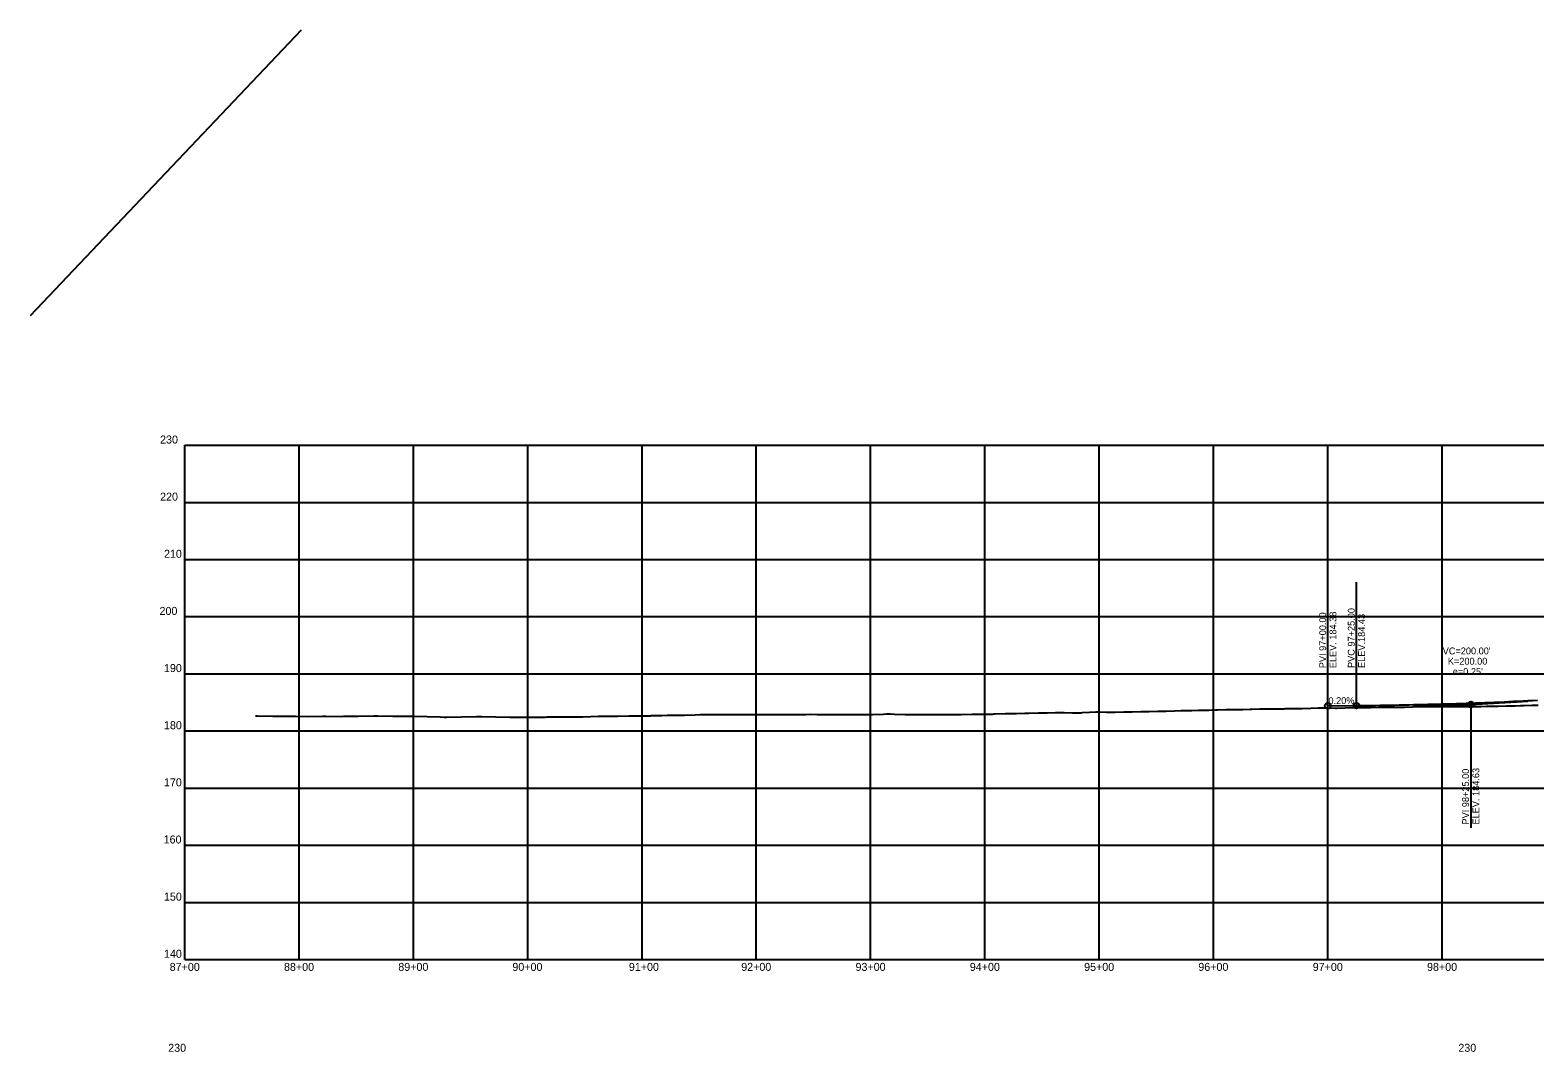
# Model space of a CAD drawing. Extents: x 1 to 1477871, y 1 to 1872901.
# Drawn here: x 1444624 to 1445940, y 1853225 to 1854119 of the extents above; entities that cross this region are included whole.
import ezdxf

# ---------------------------------------------------------------- set-up
doc = ezdxf.new("R2010")
doc.units = 0
for name, color, linetype in [('R_Axis', 7, 'Continuous'), ('R_Axis Annot', 7, 'Continuous'), ('R_Exist Surface', 7, 'Continuous'), ('R_Grid', 7, 'Continuous'), ('R_Horz Alg', 7, 'Continuous'), ('R_Vert Alg', 7, 'Continuous'), ('R_Vert Alg Annot', 7, 'Continuous')]:
    doc.layers.add(name, color=color, linetype=linetype)

msp = doc.modelspace()

# ---------------------------------------------------------------- linework, layer by layer
at = {"layer": 'R_Axis'}
for q in [(1444759.1, 1853756), (1446859.1, 1853306)]:
    msp.add_line((1444759.1, 1853306), q, dxfattribs=at)
at = {"layer": 'R_Exist Surface'}
msp.add_lwpolyline([(1444821, 1853519.1), (1444821.1, 1853519.1), (1444822.5, 1853519.1), (1444836.1, 1853518.9), (1444845.8, 1853519), (1444851.1, 1853518.9), (1444856, 1853518.9), (1444866.2, 1853518.5), (1444879.7, 1853518.8), (1444881.2, 1853518.8), (1444882.6, 1853518.8), (1444896.1, 1853518.7), (1444897.8, 1853518.8), (1444911.1, 1853518.8), (1444924.6, 1853519.1), (1444926.1, 1853519.1), (1444927.8, 1853519.2), (1444941.2, 1853518.9), (1444943, 1853518.9), (1444956.1, 1853518.8), (1444960, 1853518.8), (1444971.1, 1853518.6), (1444982.4, 1853518.3), (1444986.1, 1853518.1), (1444988.1, 1853518.1), (1445001.1, 1853518.4), (1445014.3, 1853518.7), (1445016.1, 1853518.7), (1445019, 1853518.7), (1445031.1, 1853518.3), (1445043.5, 1853518.1), (1445046.1, 1853518), (1445047.8, 1853518), (1445061.1, 1853518.1), (1445074.8, 1853518.1), (1445076.2, 1853518.2), (1445077.5, 1853518.2), (1445091.1, 1853518.3), (1445092.5, 1853518.3), (1445106.1, 1853518.4), (1445107.4, 1853518.4), (1445121.1, 1853518.8), (1445122.2, 1853518.8), (1445128.1, 1853518.8), (1445136.2, 1853518.9), (1445137.1, 1853518.9), (1445137.8, 1853518.9), (1445147.5, 1853519.2), (1445151.1, 1853519.3), (1445151.9, 1853519.3), (1445157.2, 1853519.3), (1445166.1, 1853519.3), (1445166.9, 1853519.3), (1445167.1, 1853519.4), (1445176.5, 1853519.6), (1445181.1, 1853519.7), (1445186.2, 1853519.8), (1445195.1, 1853519.9), (1445195.9, 1853519.9), (1445196.2, 1853519.9), (1445205.6, 1853520.2), (1445210, 1853520.3), (1445211.1, 1853520.3), (1445212.6, 1853520.3), (1445215.3, 1853520.3), (1445225, 1853520.4), (1445226.1, 1853520.4), (1445234.7, 1853520.3), (1445239.3, 1853520.3), (1445241.1, 1853520.3), (1445242.7, 1853520.3), (1445244.4, 1853520.3), (1445254.1, 1853520.4), (1445256.1, 1853520.4), (1445263.8, 1853520.4), (1445269.5, 1853520.4), (1445271.1, 1853520.3), (1445273.5, 1853520.3), (1445283.2, 1853520.3), (1445284.7, 1853520.3), (1445286.1, 1853520.3), (1445292.8, 1853520.4), (1445295.5, 1853520.5), (1445301.1, 1853520.5), (1445302.5, 1853520.5), (1445306.2, 1853520.6), (1445312.2, 1853520.4), (1445316.1, 1853520.3), (1445321.9, 1853520.3), (1445329.5, 1853520.3), (1445331.1, 1853520.3), (1445331.6, 1853520.3), (1445334.9, 1853520.4), (1445341.3, 1853520.3), (1445346.1, 1853520.3), (1445350, 1853520.4), (1445351, 1853520.4), (1445360.7, 1853520.4), (1445361.1, 1853520.4), (1445370.4, 1853520.8), (1445372.9, 1853520.9), (1445376.1, 1853520.9), (1445380.1, 1853520.7), (1445389.3, 1853520.4), (1445389.8, 1853520.4), (1445391, 1853520.4), (1445392.9, 1853520.5), (1445399.4, 1853520.5), (1445406, 1853520.5), (1445407.7, 1853520.5), (1445409.1, 1853520.5), (1445418.8, 1853520.5), (1445421, 1853520.5), (1445428.5, 1853520.5), (1445434.3, 1853520.5), (1445436, 1853520.5), (1445437.6, 1853520.5), (1445438.2, 1853520.5), (1445447.9, 1853520.6), (1445451, 1853520.6), (1445452.5, 1853520.7), (1445457.6, 1853520.7), (1445466, 1853520.8), (1445467.3, 1853520.9), (1445467.9, 1853520.9), (1445477, 1853521.1), (1445481, 1853521.2), (1445486.7, 1853521.3), (1445494, 1853521.4), (1445496, 1853521.4), (1445496.4, 1853521.4), (1445497.4, 1853521.5), (1445506.1, 1853521.7), (1445511, 1853521.8), (1445513.5, 1853521.8), (1445520.9, 1853522), (1445524.7, 1853522.1), (1445526, 1853522.1), (1445527.4, 1853522.1), (1445528.4, 1853522), (1445535.8, 1853521.8), (1445541, 1853521.7), (1445543.3, 1853521.9), (1445544.5, 1853522), (1445550.7, 1853522.4), (1445556, 1853522.7), (1445558.2, 1853522.6), (1445565.6, 1853522.5), (1445568.2, 1853522.5), (1445571, 1853522.3), (1445571.8, 1853522.3), (1445573, 1853522.4), (1445580.5, 1853522.6), (1445586, 1853522.8), (1445586.9, 1853522.8), (1445587.9, 1853522.8), (1445595.4, 1853522.9), (1445600.9, 1853523), (1445602, 1853523), (1445602.8, 1853523), (1445610.3, 1853523.2), (1445615.9, 1853523.3), (1445616.9, 1853523.3), (1445617.7, 1853523.4), (1445625.1, 1853523.7), (1445630.9, 1853523.9), (1445631.9, 1853524), (1445632.6, 1853524), (1445640, 1853524), (1445645.9, 1853524.1), (1445646.9, 1853524.1), (1445647.5, 1853524.1), (1445654.9, 1853524.3), (1445660.9, 1853524.4), (1445661.9, 1853524.5), (1445662.4, 1853524.5), (1445669.8, 1853524.6), (1445675.9, 1853524.8), (1445676.8, 1853524.8), (1445677.2, 1853524.8), (1445684.7, 1853524.8), (1445690.9, 1853524.9), (1445692.1, 1853524.9), (1445692.7, 1853524.9), (1445699.6, 1853525.2), (1445705.9, 1853525.4), (1445707, 1853525.4), (1445714.5, 1853525.4), (1445719.1, 1853525.4), (1445720.9, 1853525.4), (1445721.9, 1853525.5), (1445729.3, 1853525.5), (1445734.8, 1853525.6), (1445735.9, 1853525.6), (1445736.7, 1853525.6), (1445736.8, 1853525.6), (1445744.2, 1853526), (1445750.9, 1853526.3), (1445751.7, 1853526.2), (1445751.9, 1853526.2), (1445759.1, 1853526.1), (1445765.9, 1853526), (1445766.6, 1853526), (1445767, 1853526), (1445774, 1853526.2), (1445780.9, 1853526.4), (1445781.5, 1853526.4), (1445782.9, 1853526.4), (1445788.9, 1853526.5), (1445795.9, 1853526.5), (1445796.3, 1853526.5), (1445803.8, 1853526.7), (1445808.6, 1853526.8), (1445810.9, 1853526.9), (1445811.2, 1853526.9), (1445812.2, 1853526.8), (1445818.7, 1853526.9), (1445825.8, 1853526.9), (1445826.1, 1853526.9), (1445833.6, 1853527.2), (1445839.2, 1853527.4), (1445840.8, 1853527.4), (1445841, 1853527.4), (1445843.4, 1853527.5), (1445848.4, 1853527.5), (1445855.8, 1853527.5), (1445855.9, 1853527.4), (1445858.7, 1853527.4), (1445863.3, 1853527.4), (1445870.8, 1853527.4), (1445870.8, 1853527.4), (1445878.2, 1853527.4), (1445882.5, 1853527.4), (1445885.7, 1853527.3), (1445885.8, 1853527.3), (1445893.1, 1853527.5), (1445898, 1853527.6), (1445900.5, 1853527.6), (1445900.8, 1853527.6), (1445903.8, 1853527.7), (1445908, 1853527.8), (1445915.4, 1853527.9), (1445915.7, 1853527.9), (1445922.9, 1853528), (1445927.8, 1853528.2), (1445930.3, 1853528.2), (1445930.7, 1853528.2), (1445937.8, 1853528.4), (1445943.1, 1853528.5)], dxfattribs=at)
at = {"layer": 'R_Grid'}
for p, q in [((1444759.1, 1853756), (1446859.1, 1853756)), ((1444759.1, 1853756), (1446859.1, 1853756)), ((1444859.1, 1853306), (1444859.1, 1853756)), ((1444959.1, 1853306), (1444959.1, 1853756)), ((1445059.1, 1853306), (1445059.1, 1853756)), ((1445159.1, 1853306), (1445159.1, 1853756)), ((1445259.1, 1853306), (1445259.1, 1853756)), ((1445359.1, 1853306), (1445359.1, 1853756)), ((1445459.1, 1853306), (1445459.1, 1853756)), ((1445559.1, 1853306), (1445559.1, 1853756)), ((1445659.1, 1853306), (1445659.1, 1853756)), ((1445759.1, 1853306), (1445759.1, 1853756)), ((1445859.1, 1853306), (1445859.1, 1853756)), ((1444759.1, 1853706), (1446859.1, 1853706)), ((1444759.1, 1853656), (1446859.1, 1853656)), ((1444759.1, 1853606), (1446859.1, 1853606)), ((1444759.1, 1853556), (1446859.1, 1853556)), ((1444759.1, 1853506), (1446859.1, 1853506)), ((1444759.1, 1853456), (1446859.1, 1853456)), ((1444759.1, 1853406), (1446859.1, 1853406)), ((1444759.1, 1853356), (1446859.1, 1853356))]:
    msp.add_line(p, q, dxfattribs=at)
at = {"layer": 'R_Horz Alg'}
msp.add_line((1444861, 1854119.3), (1444623.8, 1853869.1), dxfattribs=at)
at = {"layer": 'R_Vert Alg'}
for p, q in [((1445884.1, 1853529.1), (1445934.1, 1853532.1)), ((1445759.1, 1853527.9), (1445784.1, 1853528.1)), ((1445834.1, 1853528.6), (1445884.1, 1853529.1))]:
    msp.add_line(p, q, dxfattribs=at)
msp.add_lwpolyline([(1445784.1, 1853528.1), (1445788.3, 1853528.2), (1445792.5, 1853528.2), (1445796.6, 1853528.3), (1445800.8, 1853528.3), (1445805, 1853528.4), (1445809.1, 1853528.5), (1445813.3, 1853528.5), (1445817.5, 1853528.6), (1445821.6, 1853528.7), (1445825.8, 1853528.8), (1445830, 1853528.9), (1445834.1, 1853529), (1445838.3, 1853529.1), (1445842.5, 1853529.2), (1445846.6, 1853529.3), (1445850.8, 1853529.4), (1445855, 1853529.5), (1445859.1, 1853529.6), (1445863.3, 1853529.7), (1445867.5, 1853529.8), (1445871.6, 1853530), (1445875.8, 1853530.1), (1445880, 1853530.3), (1445888.3, 1853530.5), (1445892.5, 1853530.7), (1445896.6, 1853530.9), (1445900.8, 1853531), (1445905, 1853531.2), (1445909.1, 1853531.3), (1445913.3, 1853531.5), (1445917.5, 1853531.7), (1445921.6, 1853531.9), (1445925.8, 1853532.1), (1445930, 1853532.3), (1445934.1, 1853532.5), (1445938.3, 1853532.7), (1445942.5, 1853532.9)], dxfattribs=at)
at = {"layer": 'R_Vert Alg Annot'}
for p, q in [((1445759.1, 1853557.9), (1445759.1, 1853635.9)), ((1445784.1, 1853558.1), (1445784.1, 1853636.1)), ((1445759.1, 1853527.9), (1445759.1, 1853557.9)), ((1445784.1, 1853528.1), (1445784.1, 1853558.1)), ((1445884.1, 1853529.1), (1445884.1, 1853499.1)), ((1445884.1, 1853499.1), (1445884.1, 1853421.1))]:
    msp.add_line(p, q, dxfattribs=at)
for centre in [(1445884.1, 1853529.1), (1445759.1, 1853527.9), (1445784.1, 1853528.1)]:
    msp.add_circle(centre, 2.5, dxfattribs=at)

# ---------------------------------------------------------------- texts
at = {"layer": 'R_Axis Annot'}
for s, height, p in [('230', 7, (1444737.5, 1853757.5)), ('230', 7, (1444737.5, 1853757.5)), ('220', 7, (1444737.5, 1853707.5)), ('210', 7, (1444740.9, 1853657.5)), ('200', 7, (1444737, 1853607.5)), ('190', 7, (1444740.9, 1853557.5)), ('180', 7, (1444740.9, 1853507.5)), ('170', 7, (1444740.9, 1853457.5)), ('160', 7, (1444740.6, 1853407.5)), ('150', 7, (1444740.9, 1853357.5)), ('140', 7, (1444740.9, 1853307.5)), ('87+00', 7, (1444745.9, 1853296)), ('-', 0.0001, (1444759.1, 1853306)), ('88+00', 7, (1444845.9, 1853296)), ('89+00', 7, (1444945.9, 1853296)), ('90+00', 7, (1445045.7, 1853296)), ('91+00', 7, (1445147.6, 1853296)), ('92+00', 7, (1445245.9, 1853296)), ('93+00', 7, (1445345.9, 1853296)), ('94+00', 7, (1445445.9, 1853296)), ('95+00', 7, (1445545.9, 1853296)), ('96+00', 7, (1445645.8, 1853296)), ('97+00', 7, (1445745.9, 1853296)), ('98+00', 7, (1445845.9, 1853296)), ('230', 7, (1444744.6, 1853225.2)), ('230', 7, (1444744.6, 1853225.2)), ('230', 7, (1445873.3, 1853225.2)), ('230', 7, (1445873.3, 1853225.2))]:
    msp.add_text(s, height=height, dxfattribs=at).set_placement(p)
at = {"layer": 'R_Vert Alg Annot'}
for s, rotation, p in [('PVC 97+25.00', 90, (1445782.6, 1853561.1)), ('PVI 97+00.00', 90, (1445757.6, 1853560.9)), ('ELEV. 184.38', 90, (1445766.6, 1853560.9)), ('ELEV.184.43', 90, (1445791.6, 1853561.1)), ('0.20%', 0.5729, (1445759.7, 1853529.4)), ('PVI 98+25.00', 90, (1445882.6, 1853424.1)), ('ELEV. 184.63', 90, (1445891.6, 1853424.1))]:
    msp.add_text(s, height=6, rotation=rotation, dxfattribs=at).set_placement(p)
for s, p in [("VC=200.00'", (1445859.6, 1853573)), ('K=200.00', (1445864.1, 1853564)), ("e=0.25'", (1445868.4, 1853555))]:
    msp.add_text(s, height=6, dxfattribs=at).set_placement(p)

doc.saveas('drawing.dxf')
